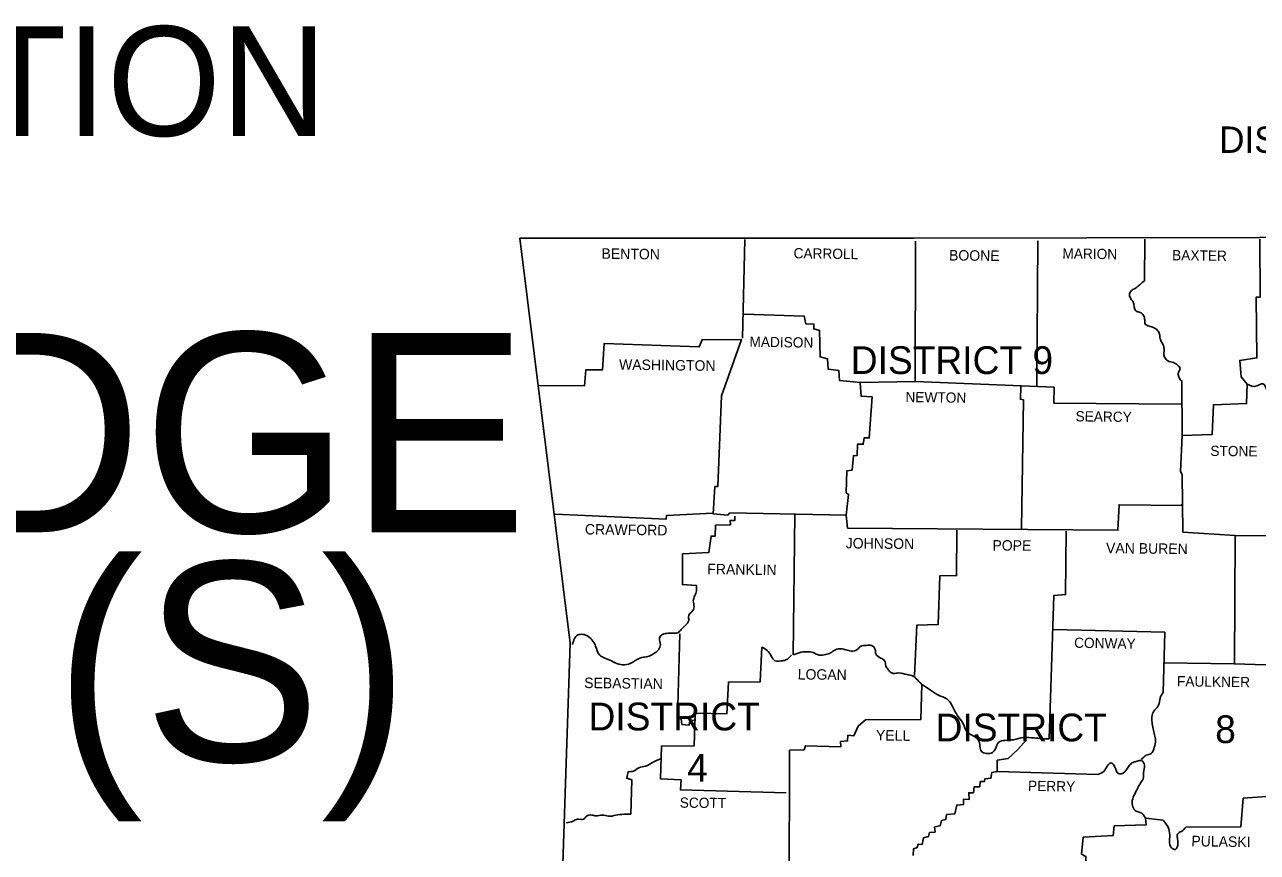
# Model space of a CAD drawing. Extents: x -31696 to 27919, y -8775 to 11152.
# Drawn here: x 8778 to 13726, y 7830 to 11152 of the extents above; entities that cross this region are included whole.
import ezdxf

# ---------------------------------------------------------------- set-up
doc = ezdxf.new("R2010")
doc.units = 0
for name, color, linetype in [('Level 1', 7, 'Continuous'), ('Level 2', 7, 'Continuous'), ('Level 3', 7, 'Continuous'), ('Level 42', 7, 'Continuous')]:
    doc.layers.add(name, color=color, linetype=linetype)

msp = doc.modelspace()

# ---------------------------------------------------------------- linework, layer by layer
at = {"layer": 'Level 1'}
for points in [[(10765.1, 10295.4), (12347.2, 10294.4), (13735.5, 10297.3), (15373.4, 10322.8), (16132.6, 10340.4)], [(10765.1, 10295.4), (10967.6, 8669.3), (10879.5, 6014.8)], [(11668.1, 10289.5), (11659.3, 9893.2)], [(11666.2, 9990.1), (11906.9, 9982.3), (11912.7, 9951), (11946, 9950), (11945, 9930.4), (11968.5, 9924.5), (11970.5, 9817.9), (12000.8, 9811.1), (12002.8, 9769), (12045.8, 9763.1), (12047.8, 9724), (12132.9, 9715.2), (12352, 9720.1), (12354, 10282.6)], [(12844.2, 10284.6), (12841.2, 9703.4)], [(13274.7, 10291.4), (13272.7, 10124.1)], [(13735.5, 10291.4), (13737.5, 10058.6), (13720.8, 10057.6), (13723.8, 9814), (13655.3, 9804.2), (13661.2, 9738.6), (13684.6, 9708.3), (13682.7, 9631), (13549.6, 9626.1), (13544.7, 9506.8), (13423.4, 9502.9), (13417.5, 9358), (13424.4, 9346.3), (13427.3, 9115.4), (13636.7, 9101.7), (13633.8, 8586.1), (13800.1, 8581.2), (13800.1, 8056.8), (13669, 8047), (13659.2, 7931.5), (13439.1, 7930.6)], [(10842.4, 9703.4), (11025.3, 9702.4), (11030.2, 9767), (11097.7, 9767), (11103.6, 9871.7), (11485.2, 9858), (11496.9, 9887.4), (11654.4, 9888.3), (11575.2, 9661.4), (11559.5, 9298.4), (11547.8, 9297.4), (11541.9, 9187.8), (11599.7, 9182.9), (11608.5, 9191.7), (12075.2, 9182.9), (12080, 9131.1)], [(12130.9, 9713.2), (12134.8, 9660.4), (12179.8, 9657.4), (12168.1, 9493.1), (12147.6, 9494), (12143.6, 9467.6), (12120.2, 9467.6), (12119.2, 9422.6), (12104.5, 9421.6), (12099.6, 9363.9), (12078.1, 9361), (12075.2, 9272.9), (12084.9, 9266.1), (12075.2, 9182.9)], [(12352, 9720.1), (12909.7, 9696.6), (12908.8, 9633), (13420.5, 9629.1)], [(12775.7, 9699.5), (12774.7, 9648.6), (12787.4, 9645.7), (12779.6, 9129.1)], [(13423.4, 9502.9), (13422.4, 9723)], [(12080, 9131.1), (13166.1, 9122.3), (13171, 9225), (13423.4, 9222.1)], [(13420.5, 9223), (13423.4, 9226)], [(10906.9, 9186.8), (11352.1, 9166.3), (11354.1, 9181.9), (11540, 9190.7)], [(11628, 9179), (11628, 9161.4), (11609.4, 9161.4), (11610.4, 9143.8), (11550.7, 9142.8), (11549.8, 9098.8), (11533.1, 9098.8), (11524.3, 9033.2), (11418.6, 9028.3), (11417.7, 8904.1), (11474.4, 8900.2)], [(11869.7, 9186.8), (11862.8, 8622.3)], [(12519.4, 9123.2), (12518.4, 8940.3), (12450.9, 8939.3), (12445, 8744.6), (12358.9, 8741.7), (12349.1, 8540.1)], [(12957.7, 9118.3), (12955.7, 8864), (12908.8, 8860), (12890.2, 8284.7)], [(13636.7, 9101.7), (14139.6, 9098.8), (14182.6, 9119.3), (14179.7, 8736.8), (14150.4, 8724), (14123.9, 8701.5), (14115.1, 8692.7), (14114.2, 8583.2), (13794.2, 8583.2)], [(12906.8, 8724), (13353.9, 8713.3), (13348.1, 8471.6)], [(11407.9, 8706.4), (11398.1, 8369.9), (11412.8, 8365.9), (11415.7, 8342.5), (11445.1, 8340.5), (11448, 8357.1), (11471.5, 8361.1)], [(11736.6, 8653.6), (11729.8, 8513.7), (11602.6, 8512.7), (11595.7, 8385.5), (11469.5, 8388.4), (11465.6, 8257.3), (11333.5, 8256.4), (11329.6, 8125.3), (11412.8, 8120.4), (11409.8, 8080.2), (11834.5, 8068.5)], [(13349, 8590), (13633.8, 8586.1)], [(12379.4, 8503.9), (12375.5, 8363), (12152.5, 8362), (12123.1, 8336.6), (12106.5, 8297.5), (12082, 8299.4), (12081, 8276.9), (12052.7, 8274), (12053.6, 8253.4), (11911.8, 8257.3), (11906.9, 8241.7), (11848.2, 8239.7), (11846.2, 7667.4)], [(12799.2, 8280.8), (12764, 8242.7), (12725.8, 8206.5), (12681.8, 8199.6), (12681.8, 8153.6), (12660.2, 8150.7), (12656.3, 8127.2), (12631.9, 8125.3), (12629.9, 8114.5), (12613.3, 8113.5), (12612.3, 8093), (12588.8, 8092), (12586.9, 8068.5), (12567.3, 8068.5), (12568.3, 8041.1), (12546.7, 8043.1), (12545.8, 8021.5), (12519.4, 8019.6), (12511.5, 7984.4), (12478.3, 7981.4), (12475.3, 7961.9), (12457.7, 7957), (12452.8, 7936.4), (12430.3, 7931.5), (12432.3, 7911), (12409.8, 7909), (12405.9, 7893.4), (12385.3, 7887.5), (12380.4, 7861.1), (12364.8, 7862.1), (12359.9, 7848.4), (12345.2, 7843.5), (12344.2, 7817.1)], [(11211.2, 7983.4), (11214.2, 8121.3), (11194.6, 8127.2), (11200.5, 8153.6)], [(13085.9, 8141.9), (12682.7, 8154.6)], [(13347.1, 7958.9), (13276.6, 7966.8), (13279.6, 7940.3), (13151.4, 7935.4), (13147.5, 7897.3), (13027.1, 7890.4), (13020.3, 7822), (13037.9, 7813.1), (13037.9, 7768.1)]]:
    msp.add_lwpolyline(points, dxfattribs=at)
for points in [[(13272.7, 10124.1), (13255.1, 10109.5), (13239.5, 10095.8), (13216, 10079.1), (13213, 10063.5), (13220.9, 10047.8), (13228.7, 10035.1), (13231.6, 10017.5), (13238.5, 10002.8), (13255.1, 9996.9), (13268.8, 9984.2), (13273.7, 9966.6), (13275.7, 9950), (13291.3, 9942.2), (13308.9, 9936.3), (13325.6, 9924.5), (13333.4, 9909.9), (13335.3, 9891.3), (13342.2, 9876.6), (13350, 9859), (13352, 9844.3), (13350, 9829.6), (13353.9, 9815.9), (13366.7, 9802.2), (13389.2, 9795.4), (13404.8, 9785.6), (13415.6, 9771.9), (13408.7, 9755.3), (13409.7, 9740.6), (13418.5, 9723)], [(13684.6, 9708.3), (13723.8, 9701.5), (13747.3, 9710.3), (13763.9, 9684.8), (13772.7, 9665.3), (13787.4, 9636.9), (13810.9, 9628.1), (13828.5, 9612.4), (13828.5, 9595.8), (13812.8, 9580.1), (13801.1, 9564.5), (13805, 9545.9), (13808.9, 9520.5), (13808.9, 9496), (13803, 9473.5), (13798.1, 9453), (13803, 9435.3), (13821.6, 9438.3), (13841.2, 9453), (13861.7, 9453), (13881.3, 9442.2), (13901.8, 9423.6), (13922.4, 9427.5), (13939, 9432.4), (13962.5, 9439.3), (13979.1, 9430.5), (13993.8, 9418.7), (14011.4, 9400.1), (14028.1, 9388.4), (14049.6, 9377.6), (14076, 9370.8), (14100.5, 9354.1), (14104.4, 9325.8), (14103.4, 9301.3), (14101.4, 9271), (14099.5, 9237.7), (14102.4, 9205.4), (14113.2, 9183.9), (14126.9, 9158.5), (14130.8, 9135), (14129.8, 9097.8)], [(11474.4, 8900.2), (11474.4, 8879.6), (11466.6, 8858.1), (11461.7, 8839.5), (11464.6, 8815), (11455.8, 8795.5), (11443.1, 8779.8), (11443.1, 8760.2), (11428.4, 8739.7), (11412.8, 8724), (11399.1, 8711.3), (11374.6, 8709.4), (11354.1, 8708.4), (11333.5, 8701.5), (11325.7, 8686.9), (11329.6, 8664.4), (11321.8, 8642.8), (11301.2, 8626.2), (11278.7, 8615.4), (11255.3, 8611.5), (11223, 8595.9), (11193.6, 8583.2), (11162.3, 8585.1), (11133, 8597.8), (11106.5, 8609.6), (11086, 8621.3), (11069.4, 8657.5), (11058.6, 8677.1), (11040, 8696.6), (11017.5, 8704.5), (10998.9, 8702.5), (10976.4, 8664.4)], [(11862.8, 8622.3), (11895.1, 8633), (11918.6, 8635), (11942.1, 8631.1), (11966.6, 8621.3), (11993, 8623.3), (12012.5, 8630.1), (12032.1, 8642.8), (12053.6, 8646.7), (12074.2, 8642.8), (12095.7, 8637), (12119.2, 8643.8), (12132.9, 8656.5), (12156.4, 8660.4), (12176.9, 8660.4), (12191.6, 8643.8), (12194.5, 8626.2), (12213.1, 8609.6), (12229.7, 8598.8), (12234.6, 8578.3), (12243.4, 8563.6), (12252.2, 8553.8), (12265, 8547.9), (12286.5, 8549.9), (12319.8, 8543), (12341.3, 8538.1), (12360.9, 8521.5), (12379.4, 8503.9)], [(11736.6, 8653.6), (11758.2, 8639.9), (11774.8, 8617.4), (11789.5, 8598.8), (11813.9, 8597.8), (11833.5, 8601.7), (11856, 8621.3)], [(12379.4, 8503.9), (12413.7, 8480.4), (12446, 8459.9), (12479.2, 8445.2), (12497.8, 8423.7), (12514.5, 8390.4), (12528.2, 8369.9), (12545.8, 8344.4), (12558.5, 8316), (12579, 8300.4), (12600.6, 8286.7), (12611.3, 8262.2), (12616.2, 8237.8), (12639.7, 8226), (12662.2, 8230.9), (12674.9, 8245.6), (12686.7, 8271), (12713.1, 8278.9), (12747.3, 8281.8), (12786.5, 8290.6), (12829.5, 8288.7), (12890.2, 8284.7)], [(13348.1, 8471.6), (13335.3, 8449.1), (13329.5, 8419.8), (13313.8, 8401.2), (13304, 8379.6), (13303.1, 8351.3), (13307.9, 8325.8), (13312.8, 8301.4), (13316.8, 8278.9), (13311.9, 8250.5), (13299.1, 8226), (13279.6, 8219.2), (13261, 8202.6)], [(11200.5, 8153.6), (11222, 8155.6), (11242.5, 8169.3), (11269.9, 8175.2), (11297.3, 8189.8), (11331.6, 8205.5)], [(13085.9, 8141.9), (13110.3, 8155.6), (13123, 8176.1), (13138.7, 8188.9), (13154.3, 8171.2), (13168, 8145.8), (13182.7, 8145.8), (13201.3, 8163.4), (13213, 8179.1), (13227.7, 8190.8), (13243.4, 8195.7), (13260, 8197.7), (13272.7, 8179.1), (13268.8, 8149.7), (13268.8, 8130.1), (13258.1, 8109.6), (13246.3, 8088.1), (13233.6, 8063.6), (13223.8, 8037.2), (13225.8, 8011.8), (13239.5, 7995.1), (13255.1, 7990.2), (13276.6, 7968.7)], [(11211.2, 7983.4), (11182.9, 7982.4), (11150.6, 7978.5), (11121.2, 7974.6), (11094.8, 7979.5), (11070.3, 7975.6), (11053.7, 7979.5), (11033.2, 7974.6), (11021.4, 7962.8), (10997, 7962.8), (10979.3, 7955), (10951, 7948.2)], [(13347.1, 7958.9), (13363.7, 7937.4), (13373.5, 7908), (13373.5, 7874.8), (13381.3, 7847.4), (13397, 7841.5), (13406.8, 7865), (13404.8, 7888.5), (13404.8, 7902.2), (13421.4, 7913.9), (13439.1, 7930.6)]]:
    msp.add_spline(points, degree=3, dxfattribs=at)

# ---------------------------------------------------------------- texts
at = {"layer": 'Level 2'}
for s, height, p in [('ARKANSAS DEPARTMENT OF TRANSPORTATION', 440, (-4001.5, 10705.3)), ('DISTRICTS 1, 2, & 6 BRIDGE', 800, (-3530.9, 9114.5)), ('PRESERVATION (2021) (S)', 800, (-3171.8, 8194.8))]:
    msp.add_text(s, height=height, dxfattribs=at).set_placement(p)
for s, height, rotation, p in [('BENTON', 42.07, 359.2527, (11092.8, 10212.2)), ('CARROLL', 41.09, 359.1481, (11863.8, 10214.2)), ('BOONE', 42.07, 359.4001, (12488, 10205.3)), ('MARION', 41.09, 359.1854, (12943, 10213.2)), ('BAXTER', 41.09, 359.2559, (13383.3, 10206.3)), ('MADISON', 41.09, 359.0906, (11686.7, 9859)), ('WASHINGTON', 42.06, 359.232, (11163.3, 9767)), ('NEWTON', 41.09, 359.2717, (12312.9, 9636.9)), ('SEARCY', 41.08, 359.2527, (12995.8, 9559.6)), ('STONE', 41.08, 359.4001, (13536.9, 9420.7)), ('CRAWFORD', 42.06, 359.2771, (11026.3, 9105.6)), ('JOHNSON', 42.07, 359.3514, (12073.2, 9049.9)), ('POPE', 42.07, 359.6155, (12662.2, 9041)), ('VAN BUREN', 42.07, 359.3508, (13118.1, 9030.3)), ('FRANKLIN', 42.07, 359.1815, (11517.5, 8946.1)), ('CONWAY', 41.08, 359.0371, (12990, 8650.7)), ('LOGAN', 42.07, 359.3969, (11880.5, 8523.5)), ('SEBASTIAN', 42.06, 359.2816, (11023.4, 8489.2)), ('FAULKNER', 41.09, 359.2486, (13402.9, 8496.1)), ('YELL', 42.07, 359.1987, (12194.5, 8278.9)), ('PERRY', 41.09, 359.0858, (12805, 8076.3)), ('SCOTT', 41.09, 359.4063, (11406.9, 8008.8)), ('PULASKI', 42.07, 359.053, (13460.6, 7854.2))]:
    msp.add_text(s, height=height, rotation=rotation, dxfattribs=at).set_placement(p)
at = {"layer": 'Level 3'}
for s, height, p in [('DISTRICT 9', 111.54, (12093.7, 9749.4)), ('DISTRICT', 111.54, (11041, 8319)), ('DISTRICT', 111.54, (12434.2, 8275)), ('8', 111.5, (13556.5, 8268.1)), ('4', 111.5, (11437.2, 8113.5))]:
    msp.add_text(s, height=height, dxfattribs=at).set_placement(p)
at = {"layer": 'Level 42'}
msp.add_text('DISTRICTS 1, 2, & 6 BRIDGE PRESERVATION (2021) (S)', height=105.809, dxfattribs=at).set_placement((13572, 10637.3))

doc.saveas('drawing.dxf')
